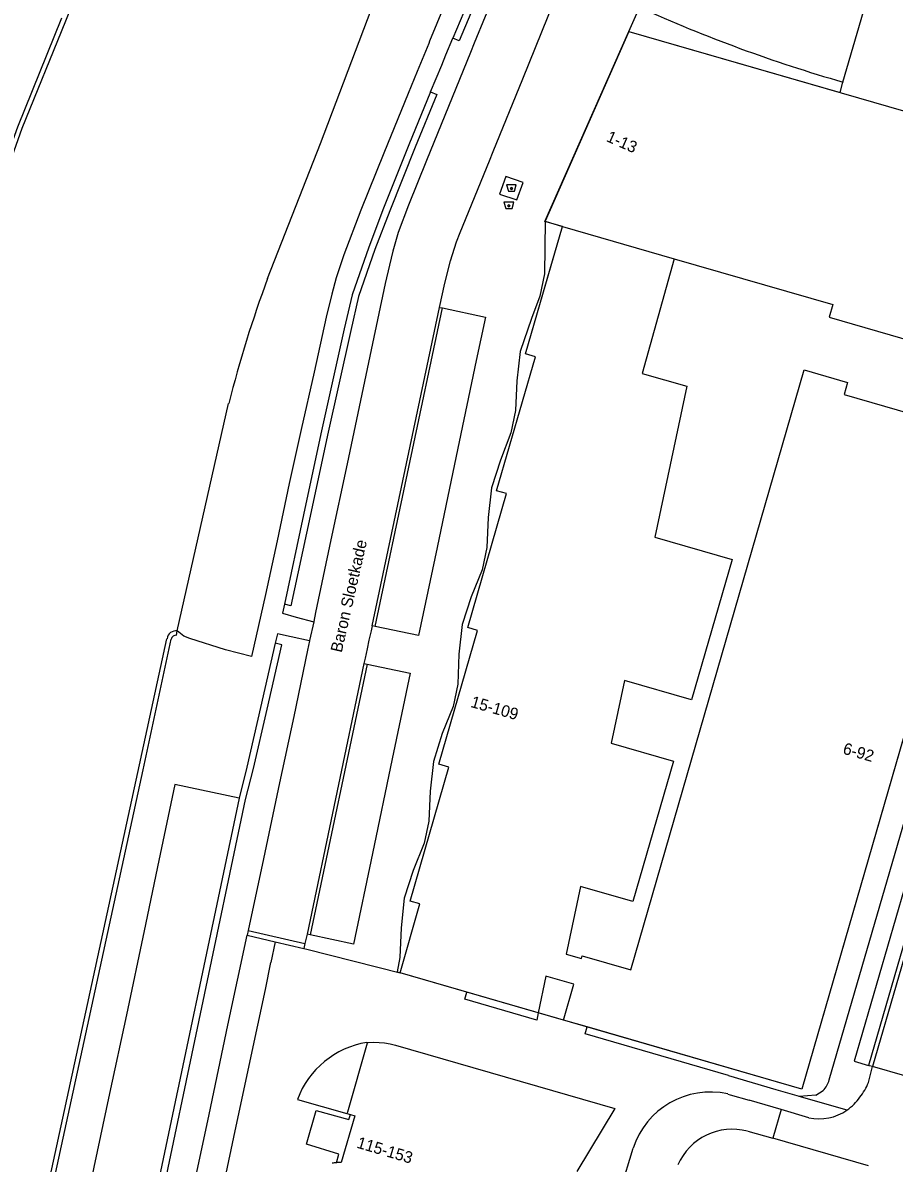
# Model space of a CAD drawing. Extents: x 194485 to 197793, y 468269 to 470822.
# Drawn here: x 194811 to 194901, y 469857.6 to 469975.4 of the extents above; entities that cross this region are included whole.
import ezdxf

# ---------------------------------------------------------------- set-up
doc = ezdxf.new("R2010")
doc.units = 0
for name, color, linetype in [('BGT begrenzing pand op maaiveld onder overbouw', 7, 'Continuous'), ('BGT grensvlak gebouwinstallatie plus 1', 7, 'Continuous'), ('BGT grensvlak pand deel overbouw', 7, 'Continuous'), ('BGT grensvlak pand min 1', 7, 'Continuous'), ('BGT grensvlak pand op maaiveld', 7, 'Continuous'), ('BGT grensvlak pand op maaiveld LR', 7, 'Continuous'), ('BGT grensvlak scheiding', 7, 'Continuous'), ('BGT grensvlak vegetatieobject', 7, 'Continuous'), ('BGT grensvlak waterdeel', 7, 'Continuous'), ('BGT grensvlak wegdeel', 7, 'Continuous'), ('BGT puntobject bak afval apart plaats', 7, 'Continuous'), ('BGT puntobject bak container', 7, 'Continuous'), ('BGT tekst huisnummerreeks', 7, 'Continuous'), ('BGT tekst openbare ruimte label weg', 7, 'Continuous')]:
    doc.layers.add(name, color=color, linetype=linetype)

msp = doc.modelspace()

# ---------------------------------------------------------------- linework, layer by layer
at = {"layer": 'BGT begrenzing pand op maaiveld onder overbouw'}
for p, q in [((194873.6, 469974.51), (194895.43, 469968.21)), ((194895.43, 469968.21), (194895.73, 469969.28)), ((194864.95, 469954.92), (194866.74, 469954.35))]:
    msp.add_line(p, q, dxfattribs=at)
msp.add_lwpolyline([(194849.97, 469877.3), (194852.03, 469884.4), (194851.01, 469884.69), (194855.01, 469898.52), (194853.99, 469898.82), (194857.99, 469912.65), (194856.97, 469912.95), (194860.97, 469926.78), (194859.95, 469927.08), (194863.95, 469940.91), (194862.93, 469941.2), (194865.78, 469951.06), (194866.74, 469954.35)], dxfattribs=at)
at = {"layer": 'BGT grensvlak gebouwinstallatie plus 1'}
msp.add_line((194839.36, 469864.21), (194844.49, 469862.74), dxfattribs=at)
msp.add_lwpolyline([(194843.4, 469857.67), (194843.66, 469858.56), (194840.31, 469859.58), (194841.31, 469863.06), (194844.69, 469862.13), (194844.84, 469862.64)], dxfattribs=at)
msp.add_arc((194848.05, 469860.94), 9.28, 99.3458, 159.3963, dxfattribs=at)
at = {"layer": 'BGT grensvlak pand deel overbouw'}
msp.add_line((194873.6, 469974.51), (194874.7, 469976.99), dxfattribs=at)
msp.add_lwpolyline([(194864.95, 469954.92), (194864.9, 469949.48), (194864.41, 469947.17), (194863.54, 469944.85), (194862.39, 469941.47), (194862.05, 469938.44), (194861.91, 469935.35), (194861.42, 469933.05), (194860.34, 469930.24), (194859.41, 469927.39), (194859.06, 469924.32), (194858.93, 469921.23), (194858.44, 469918.92), (194857.32, 469916.11), (194856.4, 469913.26), (194856.06, 469910.18), (194855.94, 469907.1), (194855.46, 469904.78), (194854.33, 469902.01), (194853.41, 469899.12), (194853.08, 469896.06), (194852.96, 469892.96), (194852.47, 469890.66), (194851.34, 469887.86), (194850.41, 469884.98), (194850.07, 469881.92), (194849.94, 469878.86), (194849.68, 469877.38), (194849.97, 469877.3)], dxfattribs=at)
msp.add_arc((194940.25, 470123.2), 160.23, 245.8515, 253.8708, dxfattribs=at)
at = {"layer": 'BGT grensvlak pand min 1'}
msp.add_lwpolyline([(194849.97, 469877.3), (194852.03, 469884.4), (194851.01, 469884.69), (194855.01, 469898.52), (194853.99, 469898.82), (194857.99, 469912.65), (194856.97, 469912.95), (194860.97, 469926.78), (194859.95, 469927.08), (194863.95, 469940.91), (194862.93, 469941.2), (194866.74, 469954.35), (194864.92, 469954.88), (194873.6, 469974.51), (194919.26, 469961.32), (194891.48, 469865.27), (194849.97, 469877.3)], dxfattribs=at)
at = {"layer": 'BGT grensvlak pand op maaiveld'}
for p, q in [((194895.73, 469969.28), (194899.92, 469983.76)), ((194873.6, 469974.51), (194864.95, 469954.92)), ((194856.88, 469875.3), (194849.97, 469877.3)), ((194864.25, 469873.16), (194856.88, 469875.3)), ((194869.3, 469871.7), (194866.87, 469872.4)), ((194844.49, 469862.74), (194844.84, 469862.64))]:
    msp.add_line(p, q, dxfattribs=at)
for points in [[(194878.3, 469951.02), (194874.97, 469939.19), (194879.61, 469937.89), (194876.29, 469922.28), (194884.28, 469919.97), (194880.08, 469905.47), (194873.15, 469907.48), (194871.77, 469901.01), (194878.22, 469899.15), (194874.03, 469884.65), (194868.63, 469886.21), (194867.15, 469879.22), (194868.71, 469878.77), (194868.8, 469879.04), (194873.8, 469877.59), (194891.72, 469939.56), (194896.21, 469938.26), (194895.84, 469937.01), (194910.96, 469932.63)], [(194878.3, 469951.02), (194894.69, 469946.32), (194894.32, 469944.99), (194912.97, 469939.6)], [(194910.96, 469932.63), (194891.48, 469865.27), (194869.3, 469871.7)], [(194866.87, 469872.4), (194867.94, 469876.11), (194865.05, 469876.95), (194864.25, 469873.16)], [(194846.54, 469870.1), (194846.56, 469870.01), (194846.59, 469870.01), (194844.53, 469862.9), (194844.53, 469862.89), (194844.49, 469862.74)], [(194846.54, 469870.1), (194846.66, 469870.1), (194847.24, 469870.12), (194847.81, 469870.1), (194848.38, 469870.04), (194848.94, 469869.94), (194849.49, 469869.8), (194872.16, 469863.28), (194868.24, 469856.75)], [(194844.84, 469862.64), (194845.31, 469862.5), (194843.89, 469857.7)]]:
    msp.add_lwpolyline(points, dxfattribs=at)
for centre, radius, start, end in [((194844.3, 469847.31), 10.4, 94.9343, 97.4399), ((194844.18, 469847.74), 9.97, 91.6449, 94.4546)]:
    msp.add_arc(centre, radius, start, end, dxfattribs=at)
at = {"layer": 'BGT grensvlak pand op maaiveld LR'}
msp.add_line((194866.74, 469954.35), (194878.3, 469951.02), dxfattribs=at)
at = {"layer": 'BGT grensvlak scheiding'}
for p, q in [((194826.89, 469912.14), (194826.96, 469912.59)), ((194812.27, 469849.04), (194825.89, 469911.79)), ((194812.27, 469849.04), (194825.89, 469911.79)), ((194823.42, 469898.26), (194826.34, 469911.73)), ((194812.73, 469848.94), (194823.42, 469898.26))]:
    msp.add_line(p, q, dxfattribs=at)
for points in [[(194827.26, 470005.62), (194827.29, 470005.61), (194827.5, 470005.47), (194823.46, 469995.62), (194818.88, 469984.24), (194815.39, 469975.57), (194810.89, 469964.48), (194809.04, 469959.22), (194808.96, 469959.25), (194808.75, 469958.62), (194808.82, 469958.6), (194806.41, 469951.63), (194802.37, 469939.9), (194798.63, 469929.16), (194794.37, 469916.82), (194790.42, 469905.46), (194786.65, 469894.58), (194784.2, 469887.31), (194784.14, 469887.34), (194783.92, 469886.71), (194784, 469886.66), (194782.91, 469883.39), (194782.57, 469882.34)], [(194814.99, 469975.88), (194810.44, 469964.62), (194808.96, 469960.48), (194808.79, 469960.54), (194807.82, 469957.71), (194808, 469957.64), (194805.89, 469951.51), (194802.06, 469940.46), (194798.03, 469928.78), (194793.99, 469917.15), (194789.81, 469905.12), (194786.25, 469894.84), (194784.15, 469888.56), (194783.95, 469888.61), (194782.99, 469885.79), (194783.18, 469885.71), (194782.49, 469883.62), (194780.41, 469877.18), (194776.68, 469864.88), (194773.33, 469852.72)]]:
    msp.add_lwpolyline(points, dxfattribs=at)
for centre, radius, start, end in [((194826.82, 469911.67), 0.932, 81.1489, 172.1601), ((194826.82, 469911.67), 0.932, 81.1489, 172.1601), ((194826.81, 469911.67), 0.48, 80.8682, 172.3383)]:
    msp.add_arc(centre, radius, start, end, dxfattribs=at)
at = {"layer": 'BGT grensvlak vegetatieobject'}
for points in [[(194863.21, 469993.06), (194861.77, 469987.71), (194860.64, 469984.36), (194856.08, 469973.54), (194855.43, 469973.81)], [(194853.13, 469968.27), (194853.78, 469968), (194851.54, 469962.55), (194848.92, 469956), (194847.38, 469952), (194845.69, 469947.13), (194844.88, 469943.64), (194842.47, 469932.82), (194840.67, 469924.46), (194838.7, 469915.19), (194838.02, 469915.36)], [(194833.34, 469895.34), (194824.3, 469852.36), (194824.99, 469852.22), (194834.02, 469895.18), (194834.83, 469898.38), (194836.23, 469904.53), (194837.76, 469911.16), (194837.08, 469911.32)]]:
    msp.add_lwpolyline(points, dxfattribs=at)
at = {"layer": 'BGT grensvlak waterdeel'}
msp.add_line((194826.96, 469912.59), (194832.26, 469936.09), dxfattribs=at)
msp.add_line((194826.96, 469912.59), (194832.26, 469936.09), dxfattribs=at)
msp.add_lwpolyline([(194836.28, 469948.99), (194841.76, 469962.94), (194847, 469976.73), (194848.85, 469981.87)], dxfattribs=at)
msp.add_lwpolyline([(194836.28, 469948.99), (194841.76, 469962.94), (194847, 469976.73), (194848.85, 469981.87)], dxfattribs=at)
msp.add_arc((194959.47, 469903.55), 131.3, 159.7495, 165.6492, dxfattribs=at)
msp.add_arc((194959.47, 469903.55), 131.3, 159.7495, 165.6492, dxfattribs=at)
at = {"layer": 'BGT grensvlak wegdeel'}
for p, q in [((194847.09, 469913.13), (194854.06, 469946.01)), ((194847.4, 469913.07), (194854.35, 469945.95)), ((194854.06, 469946.01), (194854.35, 469945.95)), ((194915.56, 469926.99), (194898.37, 469867.73)), ((194915.97, 469926.88), (194898.78, 469867.61)), ((194847.4, 469913.07), (194847.09, 469913.13)), ((194846.22, 469909.23), (194840.37, 469881.27)), ((194846.58, 469909.15), (194840.67, 469881.21)), ((194846.22, 469909.23), (194846.58, 469909.15)), ((194834.29, 469881.65), (194834.19, 469881.18)), ((194834.29, 469881.65), (194840.14, 469880.3)), ((194834.19, 469881.18), (194834.18, 469881.18)), ((194834.19, 469881.18), (194837.06, 469880.5)), ((194837.06, 469880.5), (194836.63, 469878.35)), ((194837.06, 469880.5), (194840.03, 469879.8)), ((194840.37, 469881.27), (194840.14, 469880.3)), ((194840.67, 469881.21), (194840.37, 469881.27)), ((194840.14, 469880.3), (194840.03, 469879.8)), ((194840.03, 469879.8), (194840.33, 469879.74)), ((194840.33, 469879.74), (194849.97, 469877.3)), ((194866.87, 469872.4), (194864.25, 469873.16)), ((194898.36, 469865.96), (194898.78, 469867.61)), ((194902.14, 469866.64), (194898.78, 469867.61)), ((194883.9, 469866.69), (194888.8, 469865.22)), ((194892.93, 469864.66), (194893.69, 469865.12)), ((194889.33, 469863.16), (194886.03, 469864.12)), ((194892.93, 469864.66), (194891.22, 469864.52)), ((194896.15, 469863.1), (194891.22, 469864.52)), ((194889.33, 469863.16), (194888.48, 469860.2)), ((194892.22, 469862.31), (194889.33, 469863.16)), ((194885.89, 469860.92), (194888.48, 469860.2)), ((194872.19, 469853.11), (194874.04, 469859.16)), ((194898.37, 469857.34), (194888.48, 469860.2))]:
    msp.add_line(p, q, dxfattribs=at)
for points in [[(194858.11, 469999.45), (194859.55, 469996.46), (194860.82, 469993.78), (194861.48, 469990.75), (194861.09, 469987.87), (194859.98, 469984.61), (194855.43, 469973.81)], [(194865.33, 469992.21), (194864.05, 469989.05), (194861.06, 469981.61), (194858.76, 469976.05), (194857.63, 469973.29), (194857.25, 469972.35), (194855.36, 469967.7), (194854.98, 469966.76), (194852.72, 469961.2), (194850.83, 469956.56), (194849.79, 469953.73), (194849.23, 469951.81), (194848.88, 469950.36), (194848.44, 469948.49), (194846.98, 469941.62), (194844.5, 469929.85), (194842.83, 469922.01), (194841.24, 469914.51), (194841.05, 469913.56), (194841.05, 469913.55)], [(194854.06, 469946.01), (194854.6, 469948.51), (194855.17, 469950.83), (194855.82, 469952.8), (194856.19, 469953.73), (194859.2, 469961.16), (194859.58, 469962.1), (194862.65, 469969.62), (194865.28, 469976.08), (194867.99, 469982.79), (194869.39, 469986.24), (194869.72, 469987.06), (194870.09, 469987.99), (194870.26, 469988.44), (194871.39, 469991.18), (194871.7, 469991.95)], [(194855.28, 469979.03), (194853.03, 469973.5), (194852.94, 469973.28), (194851.75, 469970.39), (194850.82, 469968.12), (194848.29, 469961.94), (194845.92, 469956.05), (194844.16, 469951.44), (194843.36, 469949.05), (194842.91, 469947.39), (194842.34, 469945.01), (194841.1, 469939.33), (194839.77, 469933.41), (194838.52, 469927.82), (194837.26, 469921.9), (194836.08, 469916.37), (194834.64, 469909.97), (194831.93, 469910.66), (194828.25, 469911.82), (194827.63, 469912.07), (194826.96, 469912.59)], [(194853.13, 469968.27), (194854.28, 469971.04), (194854.71, 469972.1), (194855.43, 469973.81)], [(194853.13, 469968.27), (194850.89, 469962.81), (194848.27, 469956.25), (194846.73, 469952.24), (194845.02, 469947.32), (194844.2, 469943.8), (194841.78, 469932.97), (194839.99, 469924.6), (194838.02, 469915.36)], [(194862.69, 469958.91), (194860.91, 469959.53), (194860.26, 469957.7), (194862.05, 469957.12), (194862.69, 469958.91)], [(194854.35, 469945.95), (194858.79, 469944.99), (194857.83, 469940.54), (194855.58, 469929.83), (194853.8, 469921.21), (194851.87, 469912.14), (194847.4, 469913.07)], [(194894.32, 469866.22), (194903.98, 469899.46), (194913.4, 469931.95), (194910.96, 469932.63)], [(194915.56, 469926.99), (194914.08, 469927.4), (194905.5, 469897.76), (194896.89, 469868.15), (194898.37, 469867.73)], [(194838.02, 469915.36), (194837.82, 469914.43), (194839.23, 469914.01), (194841.05, 469913.55)], [(194841.05, 469913.55), (194840.63, 469911.6), (194840.63, 469911.57)], [(194840.63, 469911.57), (194838.72, 469911.99), (194837.31, 469912.29), (194837.08, 469911.32)], [(194847.09, 469913.13), (194846.97, 469912.61), (194846.76, 469911.64), (194846.58, 469910.75), (194846.36, 469909.78), (194846.22, 469909.23)], [(194837.08, 469911.32), (194835.55, 469904.68), (194834.15, 469898.54), (194833.34, 469895.34)], [(194840.63, 469911.57), (194840.42, 469910.61), (194838.98, 469903.76), (194837.52, 469896.9), (194835.87, 469889.07), (194834.29, 469881.65)], [(194846.58, 469909.15), (194851.02, 469908.22), (194849.17, 469899.39), (194847.12, 469889.6), (194845.15, 469880.26), (194840.67, 469881.21)], [(194833.34, 469895.34), (194826.7, 469896.73), (194825.05, 469888.89), (194823.54, 469881.61), (194821.72, 469872.95), (194819.95, 469864.83), (194818.33, 469857.21), (194817.54, 469853.26), (194822.54, 469851.84), (194827.53, 469850.51), (194827.64, 469850.49)], [(194827.64, 469850.49), (194828.34, 469853.79), (194830.24, 469862.67), (194832.19, 469871.87), (194834.18, 469881.18)], [(194830.62, 469850.12), (194831.2, 469852.8), (194832.8, 469860.31), (194834.49, 469868.21), (194836.08, 469875.58), (194836.63, 469878.35)], [(194864.25, 469873.16), (194864.09, 469872.41), (194856.68, 469874.57), (194856.88, 469875.3)], [(194883.9, 469866.69), (194869.09, 469871), (194869.3, 469871.7)], [(194898.78, 469867.61), (194898.48, 469867.69), (194898.37, 469867.73)], [(194888.8, 469865.22), (194891.19, 469864.53), (194891.22, 469864.52)], [(194883.82, 469864.77), (194884.09, 469864.69), (194886.03, 469864.12)]]:
    msp.add_lwpolyline(points, dxfattribs=at)
for centre, radius, start, end in [((194891.5, 469867.11), 2.96, 317.6787, 342.4393), ((194892.44, 469868.39), 6.41, 321.9118, 337.7019), ((194882.02, 469856.59), 8.38, 77.5665, 162.0973), ((194893.25, 469867.33), 5.12, 304.4675, 325.6188), ((194893.25, 469867.32), 5.12, 258.3878, 304.4508), ((194884.3, 469854.99), 6.14, 75.063, 156.4023)]:
    msp.add_arc(centre, radius, start, end, dxfattribs=at)
at = {"layer": 'BGT puntobject bak afval apart plaats'}
msp.add_lwpolyline([(194861.81, 469958.01), (194861.98, 469958.68), (194860.98, 469958.68), (194861.16, 469958.01)], close=True, dxfattribs=at)
msp.add_circle((194861.48, 469958.28), 0.1, dxfattribs=at)
for start, end in [(0, 180), (180, 0)]:
    msp.add_arc((194861.48, 469958.28), 0.1, start, end, dxfattribs=at)
at = {"layer": 'BGT puntobject bak container'}
msp.add_lwpolyline([(194861.54, 469956.22), (194861.71, 469956.89), (194860.71, 469956.89), (194860.89, 469956.22)], close=True, dxfattribs=at)
msp.add_circle((194861.21, 469956.49), 0.1, dxfattribs=at)
for start, end in [(0, 180), (180, 0)]:
    msp.add_arc((194861.21, 469956.49), 0.1, start, end, dxfattribs=at)

# ---------------------------------------------------------------- texts
at = {"layer": 'BGT tekst huisnummerreeks'}
for s, rotation, p in [('1-13', 336.2, (194871.19, 469963.21)), ('15-109', 343.9, (194857.19, 469904.76)), ('6-92', 343.9, (194895.64, 469899.94)), ('115-153', 343.5, (194845.42, 469859.24))]:
    msp.add_text(s, height=1.2, rotation=rotation, dxfattribs=at).set_placement(p)
at = {"layer": 'BGT tekst openbare ruimte label weg'}
msp.add_text('Baron Sloetkade', height=1.2, rotation=77.2, dxfattribs=at).set_placement((194843.94, 469910.3))

doc.saveas('drawing.dxf')
